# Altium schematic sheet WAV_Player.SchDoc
size B; Organization: Altium Limited; Address1: L3, 12a Rodborough Rd; Address2: Frenchs Forest; Address3: NSW; Address4: Australia 2086; DocumentNumber: 1; SheetNumber: 1; SheetTotal: 2
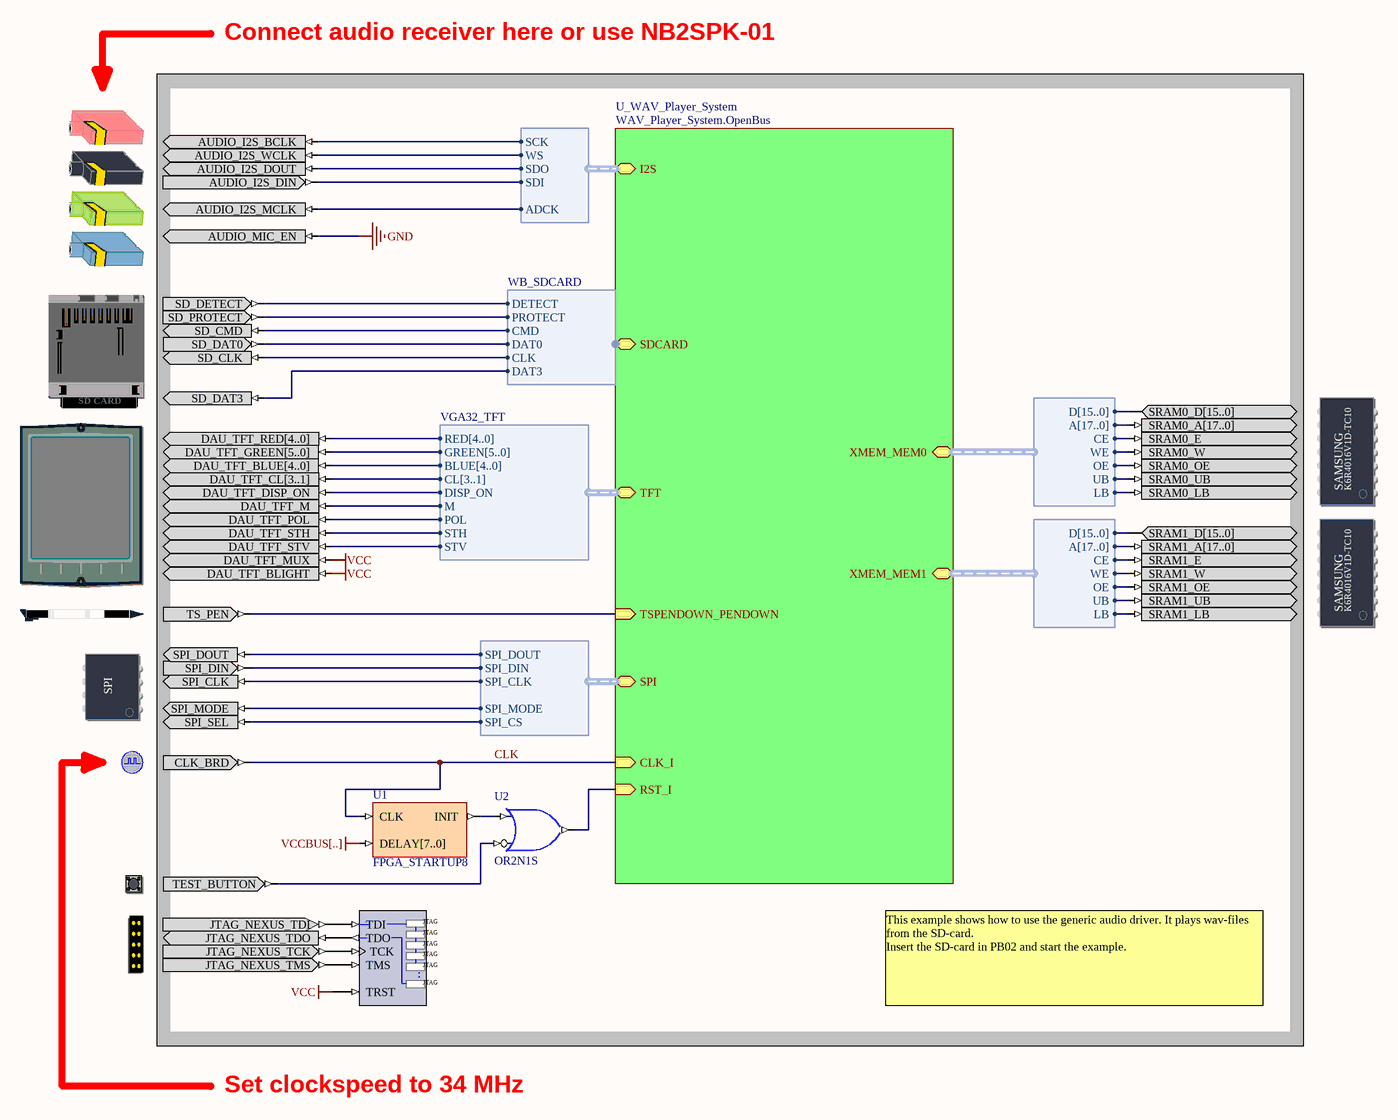
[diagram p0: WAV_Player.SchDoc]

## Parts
(Parts that share a designator on the sheet are numbered #1, #2 ... from top to bottom, then left to right.)
?#1  AUDIO_CODEC  (value not drawn)
?#2  SD_CARD  (value not drawn)
?#3  SRAM_DAUGHTER0  (value not drawn)
?#4  TFT_LCD  (value not drawn)
?#5  SRAM_DAUGHTER1  (value not drawn)
?#6  TOUCHSCREEN_PEN_DOWN  (value not drawn)
?#7  SPI_BUS  (value not drawn)
?#8  CLOCK_BOARD  (value not drawn)
?#9  TEST_BUTTON  (value not drawn)
?#10  NEXUS_JTAG_CONNECTOR  (value not drawn)
NEXUS_JTAG_PORT  NEXUS_JTAG_PORT  (value not drawn)
U1  FPGA_STARTUP8
U2  OR2N1S

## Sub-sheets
U_WAV_Player_System = WAV_Player_System.OpenBus: CLK_I (in), RST_I (in), I2S (harness I2S_W_Both), XMEM_MEM0 (harness WB_MEM_CTRL_SRAM16_A18), XMEM_MEM1 (harness WB_MEM_CTRL_SRAM16_A18), TFT (harness VGA32_TFT), TSPENDOWN_PENDOWN (in), SDCARD (harness WB_SDCARD), SPI (harness SPI_W_NB)

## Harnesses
I2S_W_Both: SCK, WS, SDO, SDI, ADCK
WB_MEM_CTRL_SRAM16_A18: D[15..0], A[17..0], CE, WE, OE, UB, LB
VGA32_TFT: RED[4..0], GREEN[5..0], BLUE[4..0], CL[3..1], DISP_ON, M, POL, STH, STV
WB_SDCARD: DETECT, PROTECT, CMD, DAT0, CLK, DAT3
SPI_W_NB: SPI_DOUT, SPI_DIN, SPI_CLK, SPI_CS, SPI_MODE

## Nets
GND: ?#1.AUDIO_MIC_EN
VCC: ?#4.DAU_TFT_BLIGHT ?#4.DAU_TFT_MUX NEXUS_JTAG_PORT.TRST
VCCBUS[..]: U1.DELAY[7..0]
CLK: ?#8.CLK_BRD U1.CLK ; sheet U_WAV_Player_System/CLK_I
Net?#1_AUDIO_I2S_BCLK: ?#1.AUDIO_I2S_BCLK ; sheet U_WAV_Player_System/I2S.SCK
Net?#1_AUDIO_I2S_DIN: ?#1.AUDIO_I2S_DIN ; sheet U_WAV_Player_System/I2S.SDI
Net?#1_AUDIO_I2S_DOUT: ?#1.AUDIO_I2S_DOUT ; sheet U_WAV_Player_System/I2S.SDO
Net?#1_AUDIO_I2S_MCLK: ?#1.AUDIO_I2S_MCLK ; sheet U_WAV_Player_System/I2S.ADCK
Net?#1_AUDIO_I2S_WCLK: ?#1.AUDIO_I2S_WCLK ; sheet U_WAV_Player_System/I2S.WS
Net?#2_SD_CLK: ?#2.SD_CLK ; sheet U_WAV_Player_System/SDCARD.CLK
Net?#2_SD_CMD: ?#2.SD_CMD ; sheet U_WAV_Player_System/SDCARD.CMD
Net?#2_SD_DAT0: ?#2.SD_DAT0 ; sheet U_WAV_Player_System/SDCARD.DAT0
Net?#2_SD_DAT3: ?#2.SD_DAT3 ; sheet U_WAV_Player_System/SDCARD.DAT3
Net?#2_SD_DETECT: ?#2.SD_DETECT ; sheet U_WAV_Player_System/SDCARD.DETECT
Net?#2_SD_PROTECT: ?#2.SD_PROTECT ; sheet U_WAV_Player_System/SDCARD.PROTECT
Net?#3_SRAM0_E: ?#3.SRAM0_E ; sheet U_WAV_Player_System/XMEM_MEM0.CE
Net?#3_SRAM0_LB: ?#3.SRAM0_LB ; sheet U_WAV_Player_System/XMEM_MEM0.LB
Net?#3_SRAM0_OE: ?#3.SRAM0_OE ; sheet U_WAV_Player_System/XMEM_MEM0.OE
Net?#3_SRAM0_UB: ?#3.SRAM0_UB ; sheet U_WAV_Player_System/XMEM_MEM0.UB
Net?#3_SRAM0_W: ?#3.SRAM0_W ; sheet U_WAV_Player_System/XMEM_MEM0.WE
Net?#4_DAU_TFT_DISP_ON: ?#4.DAU_TFT_DISP_ON ; sheet U_WAV_Player_System/TFT.DISP_ON
Net?#4_DAU_TFT_M: ?#4.DAU_TFT_M ; sheet U_WAV_Player_System/TFT.M
Net?#4_DAU_TFT_POL: ?#4.DAU_TFT_POL ; sheet U_WAV_Player_System/TFT.POL
Net?#4_DAU_TFT_STH: ?#4.DAU_TFT_STH ; sheet U_WAV_Player_System/TFT.STH
Net?#4_DAU_TFT_STV: ?#4.DAU_TFT_STV ; sheet U_WAV_Player_System/TFT.STV
Net?#5_SRAM1_E: ?#5.SRAM1_E ; sheet U_WAV_Player_System/XMEM_MEM1.CE
Net?#5_SRAM1_LB: ?#5.SRAM1_LB ; sheet U_WAV_Player_System/XMEM_MEM1.LB
Net?#5_SRAM1_OE: ?#5.SRAM1_OE ; sheet U_WAV_Player_System/XMEM_MEM1.OE
Net?#5_SRAM1_UB: ?#5.SRAM1_UB ; sheet U_WAV_Player_System/XMEM_MEM1.UB
Net?#5_SRAM1_W: ?#5.SRAM1_W ; sheet U_WAV_Player_System/XMEM_MEM1.WE
Net?#6_TS_PEN: ?#6.TS_PEN ; sheet U_WAV_Player_System/TSPENDOWN_PENDOWN
Net?#7_SPI_CLK: ?#7.SPI_CLK ; sheet U_WAV_Player_System/SPI.SPI_CLK
Net?#7_SPI_DIN: ?#7.SPI_DIN ; sheet U_WAV_Player_System/SPI.SPI_DIN
Net?#7_SPI_DOUT: ?#7.SPI_DOUT ; sheet U_WAV_Player_System/SPI.SPI_DOUT
Net?#7_SPI_MODE: ?#7.SPI_MODE ; sheet U_WAV_Player_System/SPI.SPI_MODE
Net?#7_SPI_SEL: ?#7.SPI_SEL ; sheet U_WAV_Player_System/SPI.SPI_CS
Net?#9_TEST_BUTTON: ?#9.TEST_BUTTON U2.I0
Net?#10_JTAG_NEXUS_TCK: ?#10.JTAG_NEXUS_TCK NEXUS_JTAG_PORT.TCK
Net?#10_JTAG_NEXUS_TDI: ?#10.JTAG_NEXUS_TDI NEXUS_JTAG_PORT.TDI
Net?#10_JTAG_NEXUS_TDO: ?#10.JTAG_NEXUS_TDO NEXUS_JTAG_PORT.TDO
Net?#10_JTAG_NEXUS_TMS: ?#10.JTAG_NEXUS_TMS NEXUS_JTAG_PORT.TMS
NetU1_INIT: U1.INIT U2.I1
NetU2_O: U2.O ; sheet U_WAV_Player_System/RST_I

Not connected (* = marked no-connect by the designer): ?#3 SRAM0_A[17..0] SRAM0_D[15..0]; ?#4 DAU_TFT_BLUE[4..0] DAU_TFT_CL[3..1] DAU_TFT_GREEN[5..0] DAU_TFT_RED[4..0]; ?#5 SRAM1_A[17..0] SRAM1_D[15..0]

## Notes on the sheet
- Connect audio receiver here or use NB2SPK-01
- This example shows how to use the generic audio driver. It plays wav-files from the SD-card.
  Insert the SD-card in PB02 and start the example.
- Set clockspeed to 34 MHz

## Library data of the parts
?#1 = AUDIO_CODEC: Audio Codec; PortComponent: True; IncludeInDSF: AUDIO_CS4270
?#2 = SD_CARD: Secure Digital Card Socket; PortComponent: True
?#3 = SRAM_DAUGHTER0: Free Static RAM - Daughterboard; PortComponent: True
?#4 = TFT_LCD: TFT LCD Panel; PortComponent: True
?#5 = SRAM_DAUGHTER1: Free Static RAM - Daughterboard; PortComponent: True
?#6 = TOUCH_SCREEN_PEN: TFT Touch Screen Pen; PortComponent: True
?#7 = SPI_BUS: Generic SPI Bus; PortComponent: True
?#8 = CLOCK_BOARD: Global System Clock Supply; PortComponent: True
?#9 = TEST_BUTTON: Test / Reset Button; PortComponent: True
?#10 = NEXUS_JTAG_CONNECTOR: JTAG Port; PortComponent: True
NEXUS_JTAG_PORT = NEXUS_JTAG_PORT: Soft Nexus-Chain Connector; NEXUS_JTAG_CONNECTOR: True; FunctionalClass: JTAG
U1 = FPGA_STARTUP8: FPGA Startup With 8 Bit Delay
U2 = OR2N1S: 2-Input OR Gate with Active Low A Input, Single Pin Version; XilinxEquivalent: OR2B1; FunctionalClass: Logic Primitive; PortSize: 2; ArchiveName: GENERIC; VHDLIB_SIM: GENERIC_LIB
